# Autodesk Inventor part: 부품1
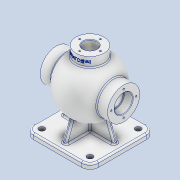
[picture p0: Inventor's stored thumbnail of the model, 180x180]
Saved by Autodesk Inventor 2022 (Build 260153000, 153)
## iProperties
Created: 2024-04
Part Number: 부품1
Material: 알루미늄 6061
Document SubType Name: Modeling
Designer: Admin
Density: 2.7 g/cm^3
Appearance: 알루미늄 - 평지
Mass: 1525.37 g
Surface Area: 1189.43 cm^2
Volume: 564.952 cm^3
Author: Admin
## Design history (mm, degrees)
sketch "스케치2"
  geometry: L1 (-403.888, 0)-(403.888, 0) reference; L2 (0, -37.2)-(0, 69.2) reference; L3 (-288.492, 0)-(288.492, 0); C1 r 22 at (0, 0); A1 r 54 centre (0, 0) between (54, 0) and (-54, 0); 3 further points
  constraints: 2 centre point, 2 coincident, 2 end point, 2 point on circle, 2 point on line, 1 horizontal, 1 midpoint
  dimensions: "d6" = 54 radius of A1; "d16" = 44 diameter of C1
revolve "회전1" sketch "스케치2" stored, may be unused: angle "d7" = 90 deg
node "작업 평면1"
sketch "스케치3"
  geometry: C1 r 27 at (0, 0); 1 further point
  constraints: 1 centre point, 1 coincident
  dimensions: "d9" = 54 diameter of C1
extrude "돌출1" join sketch "스케치3" stored distance "d10" = 16; taper "d11" = 0 deg
node "작업 평면2"
sketch "스케치4"
  geometry: L1 (-43.4, 0)-(43.4, 0) reference; L2 (0, -43.4)-(0, 43.4) reference; C1 r 31 at (0, 0); 1 further point
  constraints: 1 centre point, 1 coincident
  dimensions: "d13" = 62 diameter of C1
extrude "돌출2" join sketch "스케치4" stored distance "d14" = 10; taper "d15" = 0 deg
sketch "스케치5"
  geometry: L1 (-58.813, 0)-(58.813, 0); A1 r 44 centre (0, 0) between (44, 0) and (-44, 0); 2 further points
  constraints: 2 coincident, 2 end point, 2 point on circle, 2 point on line, 1 centre point, 1 horizontal, 1 midpoint
  dimensions: "d18" = 44 radius of A1
revolve "회전2" sketch "스케치5" stored, may be unused: angle "d19" = 90 deg
sketch "스케치6"
  geometry: L1 (-97.524, 0)-(97.524, 0); L2 (-65, -31)-(-65, 31) reference; L3 (-65, 17.5)-(-49, 17.5); L4 (-49, 17.5)-(-49, 0); L5 (-49, 0)-(-65, 0); L6 (-65, 0)-(-65, 17.5); L7 (-49, 15)-(-39, 15); L8 (-39, 15)-(-39, 0); L9 (-39, 0)-(-49, 0); L10 (-49, 0)-(-49, 15); L11 (0, -77.8)-(0, 88.8) reference; L12 (65, 17.5)-(49, 17.5); L13 (65, 0)-(65, 17.5); L14 (49, 0)-(65, 0); L15 (49, 0)-(49, 15); L16 (49, 15)-(39, 15); L17 (49, 17.5)-(49, 0); L18 (39, 15)-(39, 0); L19 (39, 0)-(49, 0); C1 r 44 at (0, 0) reference; 7 further points
  constraints: 34 end point, 8 symmetric about line, 5 point on line, 4 parallel, 3 horizontal, 2 perpendicular, 1 coincident, 1 midpoint, 1 other
  dimensions: "d20" = 35 diameter of L3 L1; "d21" = 30 diameter of L7 L1; "d22" = 16 distance between parallel lines of L4 L2; "d23" = 10 distance between parallel lines of L4 L8
revolve "회전3" sketch "스케치6" stored, may be unused: angle "d24" = 90 deg
sketch "스케치7"
  geometry: 1 further point
sketch "스케치8"
  geometry: 1 further point
sketch "스케치9"
  geometry: C1 r 13 at (0, 0); 1 further point
  constraints: 1 centre point, 1 coincident
  dimensions: "d25" = 26 diameter of C1
extrude "돌출3" cut sketch "스케치9" stored distance "d26" = 10; taper "d27" = 0 deg
node "작업 평면3"
sketch "스케치10"
  geometry: L1 (-62.5, 62.5)-(62.5, 62.5); L2 (62.5, 62.5)-(62.5, -62.5); L3 (62.5, -62.5)-(-62.5, -62.5); L4 (-62.5, -62.5)-(-62.5, 62.5); L5 (-62.5, 62.5)-(62.5, -62.5); L6 (62.5, 62.5)-(-62.5, -62.5); 1 further point
  constraints: 12 end point, 2 midpoint, 2 parallel, 1 horizontal, 1 perpendicular
  dimensions: "d29" = 125 distance of L2.end L3.end; "d30" = 125 distance of L1.end L2.end
extrude "돌출4" join sketch "스케치10" distance "d31" = 10; taper "d32" = 0 deg
sketch "스케치11"
  geometry: L1 (46.765, 27)-(65, 27) reference; L2 (65, 27)-(65, 13) reference; L3 (65, 13)-(42.036, 13) reference; L4 (42.036, -13)-(65, -13) reference; L5 (65, -13)-(65, -27) reference; L6 (65, -27)-(46.765, -27) reference; L7 (-85, 62.5)-(-75, 62.5) reference; L8 (-75, 62.5)-(-75, -62.5) reference; L9 (-75, -62.5)-(-85, -62.5) reference; L10 (-85, -62.5)-(-85, 62.5) reference; L11 (-38.966, -37.385)-(-75, -50.5); L12 (-115, 0)-(95, 0) reference; L13 (-38.966, 37.385)-(-75, 50.5); L14 (-75, -50.5)-(-75, 50.5); L15 (-75, 62.5)-(-75, -62.5) reference; A1 r 54 centre (0, 0) between (46.765, 27) and (0, 54) reference; A2 r 54 centre (0, 0) between (0, 54) and (0, -54) reference; A3 r 44 centre (0, 0) between (42.036, 13) and (0, 44) reference; A4 r 44 centre (0, 0) between (0, 44) and (0, -44) reference; A5 r 44 centre (0, 0) between (0, -44) and (42.036, -13) reference; A6 r 54 centre (0, 0) between (0, -54) and (46.765, -27) reference; A7 r 54 centre (0, 0) between (54, 0) and (-38.966, -37.385); A8 r 54 centre (0, 0) between (-38.966, 37.385) and (54, 0); 2 further points
  constraints: 6 end point, 6 point on circle, 2 centre point, 2 point on line, 2 symmetric about line, 1 coincident, 1 collinear, 1 other
  dimensions: "d33" = 20 deg angle of L9 L11; "d34" = 12 distance from line of L11.end L9
extrude "돌출5" join sketch "스케치11" stored distance "d35" = 8; taper "d36" = 0 deg
sketch "스케치15"
  geometry: L1 (44.215, 31)-(65, 31) reference; L2 (65, 31)-(65, 17.5) reference; L3 (65, 17.5)-(49, 17.5) reference; L4 (49, 17.5)-(49, 15) reference; L5 (49, 15)-(41.364, 15) reference; L6 (13, 42.036)-(13, 65) reference; L7 (13, 65)-(27, 65) reference; L8 (27, 65)-(27, 46.765) reference; L9 (-65, 31)-(-44.215, 31) reference; L10 (-27, 46.765)-(-27, 65) reference; L11 (-27, 65)-(-13, 65) reference; L12 (-13, 65)-(-13, 42.036) reference; L13 (-41.364, 15)-(-49, 15) reference; L14 (-49, 15)-(-49, 17.5) reference; L15 (-49, 17.5)-(-65, 17.5) reference; L16 (-65, 17.5)-(-65, 31) reference; L17 (-44.215, -31)-(-65, -31) reference; L18 (-65, -31)-(-65, -17.5) reference; L19 (-65, -17.5)-(-49, -17.5) reference; L20 (-49, -17.5)-(-49, -15) reference; L21 (-49, -15)-(-41.364, -15) reference; L22 (41.364, -15)-(49, -15) reference; L23 (49, -15)-(49, -17.5) reference; L24 (49, -17.5)-(65, -17.5) reference; L25 (65, -17.5)-(65, -31) reference; L26 (65, -31)-(44.215, -31) reference; L27 (-4, -54)-(0, -54) reference; L28 (-4, -75)-(-4, -54) reference; L29 (-62.5, -75)-(-4, -75) reference; L30 (-62.5, -85)-(-62.5, -75) reference; L31 (62.5, -85)-(-62.5, -85) reference; L32 (62.5, -75)-(62.5, -85) reference; L33 (4, -75)-(62.5, -75) reference; L34 (4, -54)-(4, -75) reference; L35 (0, -54)-(4, -54) reference; L36 (35.644, -34.183)-(50.5, -75); L37 (50.5, -75)-(0, -75); L38 (0, -75)-(0, -49.386); A1 r 44 centre (0, 0) between (41.364, 15) and (13, 42.036) reference; A2 r 54 centre (0, 0) between (44.215, 31) and (27, 46.765) reference; A3 r 54 centre (0, 0) between (-27, 46.765) and (-44.215, 31) reference; A4 r 44 centre (0, 0) between (-13, 42.036) and (-41.364, 15) reference; A5 r 44 centre (0, 0) between (-41.364, -15) and (41.364, -15) reference; A6 r 54 centre (0, 0) between (-44.215, -31) and (0, -54) reference; A7 r 54 centre (0, 0) between (0, -54) and (44.215, -31) reference; A8 r 49.386 centre (0, 0) between (0, -49.386) and (35.644, -34.183); 3 further points
  constraints: 6 end point, 2 point on circle, 1 centre point, 1 coincident, 1 collinear, 1 horizontal, 1 perpendicular
  dimensions: "d40" = 20 deg angle of L32 L36; "d41" = 12 distance from line of L36.end L32
extrude "돌출6" join sketch "스케치15" stored distance "d42" = 8; taper "d43" = 0 deg
sketch "스케치16" dims "d44" = 48
  geometry: L1 (0, -115)-(0, 95) reference; L2 (87.5, 0)-(-87.5, 0) reference; 3 further points
  constraints: 2 vertical alignment, 1 coincident, 2 other
hole "구멍1" sketch "스케치16" at (0, 24) diameter "d45" = 3.242; stored, may be unused: countersink angle "d49" = 90 deg, drill point angle "d51" = 90 deg; dims "d46" = 12, "d47" = 4, "d48" = 2, "d50" = 15
sketch "스케치17" dims "d55" = 40
  geometry: 3 further points
  constraints: 2 vertical alignment, 1 coincident, 2 other
hole "구멍2" sketch "스케치17" at (0, -20) diameter "d56" = 3.242; stored, may be unused: countersink angle "d60" = 90 deg, drill point angle "d62" = 90 deg; dims "d57" = 9, "d58" = 4, "d59" = 2, "d61" = 11
sketch "스케치18"
  geometry: 1 further point
fillet "모깎기1" dims "d66" = 16
sketch "스케치19"
  geometry: C1 r 5.5 at (-46.5, -46.5); C2 r 5.5 at (-46.5, 46.5); C3 r 5.5 at (46.5, -46.5); C4 r 5.5 at (46.5, 46.5); A1 r 16 centre (-46.5, -46.5) between (-62.5, -46.5) and (-46.5, -62.5) reference; A2 r 16 centre (-46.5, 46.5) between (-46.5, 62.5) and (-62.5, 46.5) reference; A3 r 16 centre (46.5, -46.5) between (46.5, -62.5) and (62.5, -46.5) reference; A4 r 16 centre (46.5, 46.5) between (62.5, 46.5) and (46.5, 62.5) reference; 1 further point
  constraints: 4 centre point, 4 coincident
  dimensions: "d67" = 11 diameter of C1; "d68" = 11 diameter of C2; "d69" = 11 diameter of C3; "d70" = 11 diameter of C4
extrude "돌출7" cut sketch "스케치19" extent not by distance; stored distance "d71" = 0; taper "d72" = 0 deg
node "작업 평면4"
sketch "스케치20"
  geometry: L1 (-91, 0)-(91, 0) reference; L2 (0, -115)-(0, 95) reference; L3 (27, 65)-(-27, 65) reference; 2 further points
  constraints: 1 point on line, 1 other
  dimensions: "d74" = 9 distance from line of L3 point (0, 56)
feature "엠보싱1" sketch "스케치20" dims "d75" = 0.5, "d76" = 0
chamfer "모따기1" distance "d77" = 1; stored, may be unused: second distance "d78" = 2, angle "d79" = 45 deg
fillet "모깎기2" dims "d80" = 3
fillet "모깎기3" dims "d81" = 3
node "솔리드1"
mirror "미러1"
mirror "미러2"
pattern_circular "원형 패턴1" dims angle "d53" = 360 deg
mirror "미러3"
pattern_circular "원형 패턴2" dims angle "d64" = 360 deg
node "절단 모서리 투영1"
node "절단 모서리 투영3"
feature "A9D066F2-1C7D-4E18-AEED-F7BC21143FA4" dims "d45" = 3.242, "d46" = 12, "d47" = 4, "d48" = 2, "d49" = 90 deg, "d50" = 15, "d51" = 90 deg
other parameters: "d8" = 65, "d12" = -65, "d73" = 86.5
